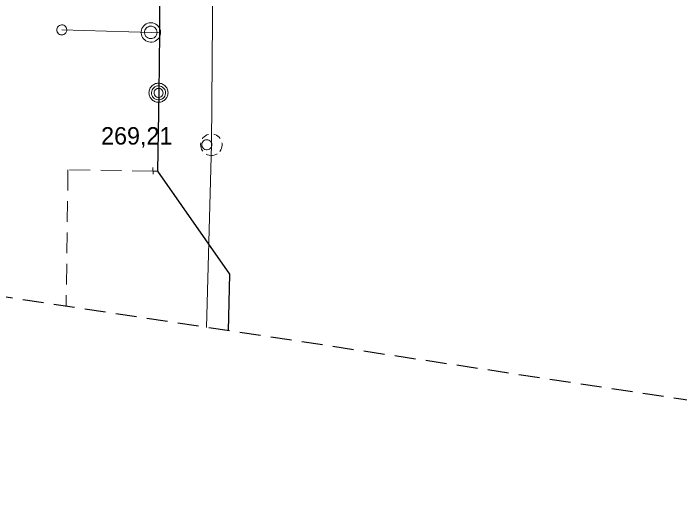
# Model space of a CAD drawing. Extents: x -732096 to -731933, y -1048703 to -1047964.
# Drawn here: x -731994.1 to -731963.51, y -1048703.26 to -1048680.91 of the extents above; entities that cross this region are included whole.
import ezdxf

# ---------------------------------------------------------------- set-up
doc = ezdxf.new("R2010")
doc.units = 0
doc.header["$LTSCALE"] = 0.32
doc.linetypes.add('MEDIUM_DASHED', pattern=[4.5, 3, -1.5])
doc.layers.add('1', color=7, linetype='Continuous')
for name, color, linetype, lineweight in [('18', 7, 'Continuous', 13), ('20', 7, 'Continuous', 13), ('63', 7, 'MEDIUM_DASHED', 25), ('8', 7, 'Continuous', 13)]:
    doc.layers.add(name, color=color, linetype=linetype, lineweight=lineweight)

msp = doc.modelspace()

# ---------------------------------------------------------------- linework, layer by layer
at = {"layer": '18'}
for points in [[(-731985.142, -1048686.473), (-731985.213, -1048686.499), (-731985.281, -1048686.536), (-731985.342, -1048686.583), (-731985.395, -1048686.639), (-731985.419, -1048686.672)], [(-731984.605, -1048686.668), (-731984.654, -1048686.609), (-731984.711, -1048686.558), (-731984.775, -1048686.515), (-731984.845, -1048686.484), (-731984.894, -1048686.469)], [(-731985.496, -1048686.856), (-731985.504, -1048686.933), (-731985.5, -1048687.01), (-731985.485, -1048687.086), (-731985.458, -1048687.157), (-731985.419, -1048687.224), (-731985.404, -1048687.247)], [(-731984.624, -1048687.254), (-731984.581, -1048687.19), (-731984.549, -1048687.12), (-731984.528, -1048687.046), (-731984.518, -1048686.97), (-731984.521, -1048686.893), (-731984.527, -1048686.858)], [(-731985.25, -1048687.379), (-731985.181, -1048687.412), (-731985.106, -1048687.433), (-731985.03, -1048687.441), (-731984.953, -1048687.438), (-731984.878, -1048687.423), (-731984.805, -1048687.397), (-731984.744, -1048687.363)]]:
    msp.add_lwpolyline(points, dxfattribs=at)
msp.add_lwpolyline([(-731984.988, -1048686.949), (-731984.994, -1048686.897), (-731985.012, -1048686.847), (-731985.04, -1048686.803), (-731985.078, -1048686.766), (-731985.123, -1048686.739), (-731985.173, -1048686.723), (-731985.225, -1048686.718), (-731985.277, -1048686.725), (-731985.326, -1048686.744), (-731985.37, -1048686.774), (-731985.405, -1048686.813), (-731985.431, -1048686.858), (-731985.446, -1048686.909), (-731985.449, -1048686.961), (-731985.441, -1048687.013), (-731985.42, -1048687.061), (-731985.39, -1048687.104), (-731985.35, -1048687.139), (-731985.304, -1048687.163), (-731985.253, -1048687.177), (-731985.201, -1048687.179), (-731985.149, -1048687.169), (-731985.101, -1048687.147), (-731985.059, -1048687.115), (-731985.026, -1048687.075), (-731985.002, -1048687.028), (-731984.99, -1048686.977)], close=True, dxfattribs=at)
at = {"layer": '20'}
msp.add_line((-731985.238, -1048695.344), (-731985, -1048686.94), dxfattribs=at)
msp.add_line((-731985.238, -1048695.344), (-731985, -1048686.94), dxfattribs=at)
msp.add_lwpolyline([(-731985, -1048686.94), (-731984.895, -1048673.539), (-731984.774, -1048658.239), (-731984.62, -1048638.44)], dxfattribs=at)
msp.add_lwpolyline([(-731985, -1048686.94), (-731984.895, -1048673.539), (-731984.774, -1048658.239), (-731984.62, -1048638.44)], dxfattribs=at)
at = {"layer": '63'}
msp.add_lwpolyline([(-732027.835, -1048396.578), (-731958.19, -1048580.745), (-731958.189, -1048580.746), (-731932.909, -1048703.246), (-731932.908, -1048703.248), (-731932.909, -1048703.25), (-731932.909, -1048703.251), (-731932.91, -1048703.253), (-731932.911, -1048703.255), (-731932.913, -1048703.256), (-731932.914, -1048703.257), (-731932.916, -1048703.257), (-731932.918, -1048703.258), (-731932.92, -1048703.258), (-732030.18, -1048688.546), (-732030.182, -1048688.545), (-732030.184, -1048688.545), (-732030.185, -1048688.543), (-732030.186, -1048688.542), (-732030.187, -1048688.54), (-732030.188, -1048688.538), (-732095.318, -1048413.733)], dxfattribs=at)
at = {"layer": '8'}
for p, q in [((-731987.687, -1048688.304), (-731987.693, -1048688)), ((-731987.487, -1048688.16), (-731987.69, -1048688.159))]:
    msp.add_line(p, q, dxfattribs=at)
at = {"layer": '8', "lineweight": 25}
for points in [[(-731986.969, -1048642.05), (-731986.984, -1048644.243), (-731987.12, -1048663.55), (-731987.35, -1048670.27), (-731987.388, -1048681.801), (-731987.43, -1048684.57)], [(-731987.43, -1048684.57), (-731987.487, -1048688.16), (-731984.18, -1048692.889), (-731984.235, -1048695.496)]]:
    msp.add_lwpolyline(points, dxfattribs=at)
at = {"layer": '8'}
for points in [[(-731987.79, -1048681.342), (-731987.863, -1048681.348), (-731987.934, -1048681.366), (-731988.001, -1048681.395), (-731988.062, -1048681.435), (-731988.117, -1048681.484), (-731988.162, -1048681.541), (-731988.197, -1048681.605), (-731988.222, -1048681.674), (-731988.235, -1048681.746), (-731988.236, -1048681.82), (-731988.225, -1048681.892), (-731988.202, -1048681.962), (-731988.169, -1048682.026), (-731988.125, -1048682.085), (-731988.072, -1048682.136), (-731988.012, -1048682.177), (-731987.945, -1048682.208), (-731987.875, -1048682.228), (-731987.802, -1048682.236), (-731987.729, -1048682.233), (-731987.658, -1048682.217), (-731987.59, -1048682.19), (-731987.527, -1048682.152), (-731987.472, -1048682.104), (-731987.425, -1048682.048), (-731987.388, -1048681.985), (-731987.361, -1048681.917), (-731987.346, -1048681.845), (-731987.343, -1048681.772), (-731987.352, -1048681.699), (-731987.373, -1048681.629), (-731987.405, -1048681.563), (-731987.447, -1048681.503), (-731987.498, -1048681.451), (-731987.558, -1048681.408), (-731987.623, -1048681.375), (-731987.693, -1048681.354), (-731987.765, -1048681.344)], [(-731992.11, -1048681.666), (-731992.105, -1048681.718), (-731992.089, -1048681.768), (-731992.062, -1048681.813), (-731992.026, -1048681.851), (-731991.981, -1048681.88), (-731991.932, -1048681.897), (-731991.88, -1048681.904), (-731991.828, -1048681.899), (-731991.778, -1048681.881), (-731991.733, -1048681.853), (-731991.697, -1048681.815), (-731991.67, -1048681.771), (-731991.653, -1048681.72), (-731991.649, -1048681.668), (-731991.655, -1048681.616), (-731991.674, -1048681.567), (-731991.703, -1048681.523), (-731991.742, -1048681.487), (-731991.787, -1048681.462), (-731991.838, -1048681.446), (-731991.89, -1048681.443), (-731991.942, -1048681.451), (-731991.991, -1048681.471), (-731992.034, -1048681.502), (-731992.068, -1048681.541), (-731992.093, -1048681.587), (-731992.107, -1048681.638)], [(-731987.79, -1048681.504), (-731987.848, -1048681.509), (-731987.904, -1048681.527), (-731987.955, -1048681.555), (-731987.999, -1048681.594), (-731988.035, -1048681.64), (-731988.06, -1048681.693), (-731988.074, -1048681.75), (-731988.076, -1048681.809), (-731988.066, -1048681.866), (-731988.044, -1048681.921), (-731988.012, -1048681.97), (-731987.971, -1048682.011), (-731987.922, -1048682.043), (-731987.867, -1048682.065), (-731987.81, -1048682.075), (-731987.751, -1048682.074), (-731987.694, -1048682.06), (-731987.641, -1048682.035), (-731987.595, -1048681.999), (-731987.556, -1048681.955), (-731987.528, -1048681.904), (-731987.51, -1048681.848), (-731987.504, -1048681.79), (-731987.51, -1048681.732), (-731987.527, -1048681.676), (-731987.556, -1048681.625), (-731987.595, -1048681.581), (-731987.641, -1048681.546), (-731987.694, -1048681.521), (-731987.751, -1048681.507)], [(-731987.113, -1048684.567), (-731987.119, -1048684.506), (-731987.137, -1048684.446), (-731987.166, -1048684.391), (-731987.205, -1048684.343), (-731987.252, -1048684.303), (-731987.306, -1048684.273), (-731987.365, -1048684.253), (-731987.427, -1048684.246), (-731987.489, -1048684.25), (-731987.549, -1048684.266), (-731987.604, -1048684.294), (-731987.654, -1048684.331), (-731987.695, -1048684.378), (-731987.727, -1048684.431), (-731987.747, -1048684.49), (-731987.757, -1048684.551), (-731987.754, -1048684.613), (-731987.739, -1048684.673), (-731987.713, -1048684.73), (-731987.677, -1048684.78), (-731987.631, -1048684.823), (-731987.579, -1048684.855), (-731987.521, -1048684.878), (-731987.46, -1048684.888), (-731987.398, -1048684.887), (-731987.337, -1048684.874), (-731987.28, -1048684.849), (-731987.229, -1048684.814), (-731987.185, -1048684.77), (-731987.151, -1048684.718), (-731987.127, -1048684.661), (-731987.115, -1048684.6)], [(-731987.227, -1048684.567), (-731987.233, -1048684.518), (-731987.25, -1048684.471), (-731987.278, -1048684.43), (-731987.316, -1048684.397), (-731987.36, -1048684.373), (-731987.408, -1048684.361), (-731987.458, -1048684.36), (-731987.506, -1048684.372), (-731987.551, -1048684.394), (-731987.589, -1048684.427), (-731987.618, -1048684.467), (-731987.637, -1048684.514), (-731987.644, -1048684.563), (-731987.639, -1048684.613), (-731987.622, -1048684.66), (-731987.595, -1048684.702), (-731987.558, -1048684.736), (-731987.515, -1048684.76), (-731987.467, -1048684.774), (-731987.417, -1048684.775), (-731987.368, -1048684.765), (-731987.323, -1048684.743), (-731987.284, -1048684.711), (-731987.254, -1048684.672), (-731987.235, -1048684.626), (-731987.227, -1048684.576)]]:
    msp.add_lwpolyline(points, close=True, dxfattribs=at)
for points in [[(-731987.388, -1048681.801), (-731987.78, -1048681.79), (-731991.879, -1048681.664)], [(-731987, -1048684.559), (-731987.002, -1048684.514), (-731987.009, -1048684.469), (-731987.021, -1048684.424), (-731987.037, -1048684.382), (-731987.058, -1048684.341), (-731987.083, -1048684.302), (-731987.112, -1048684.267), (-731987.144, -1048684.234), (-731987.18, -1048684.206), (-731987.218, -1048684.181), (-731987.259, -1048684.16), (-731987.302, -1048684.143), (-731987.346, -1048684.131), (-731987.391, -1048684.124), (-731987.437, -1048684.122), (-731987.483, -1048684.124), (-731987.528, -1048684.131), (-731987.572, -1048684.143), (-731987.615, -1048684.16), (-731987.656, -1048684.181), (-731987.694, -1048684.206), (-731987.73, -1048684.234), (-731987.762, -1048684.267), (-731987.791, -1048684.302), (-731987.816, -1048684.341), (-731987.837, -1048684.382), (-731987.853, -1048684.424), (-731987.865, -1048684.469), (-731987.872, -1048684.514), (-731987.875, -1048684.56), (-731987.872, -1048684.605), (-731987.865, -1048684.65), (-731987.853, -1048684.695), (-731987.837, -1048684.737), (-731987.816, -1048684.778), (-731987.791, -1048684.817), (-731987.762, -1048684.852), (-731987.73, -1048684.885), (-731987.694, -1048684.913), (-731987.656, -1048684.938), (-731987.615, -1048684.959), (-731987.572, -1048684.976), (-731987.528, -1048684.987), (-731987.483, -1048684.995), (-731987.437, -1048684.997), (-731987.391, -1048684.995), (-731987.346, -1048684.987), (-731987.302, -1048684.976), (-731987.259, -1048684.959), (-731987.218, -1048684.938), (-731987.18, -1048684.913), (-731987.144, -1048684.885), (-731987.112, -1048684.852), (-731987.083, -1048684.817), (-731987.058, -1048684.778), (-731987.037, -1048684.737), (-731987.021, -1048684.695), (-731987.009, -1048684.65), (-731987.002, -1048684.605), (-731987, -1048684.56)]]:
    msp.add_lwpolyline(points, dxfattribs=at)
at = {"layer": '8', "linetype": 'MEDIUM_DASHED'}
msp.add_lwpolyline([(-731987.69, -1048688.159), (-731991.594, -1048688.099), (-731991.68, -1048694.37)], dxfattribs=at)

# ---------------------------------------------------------------- texts
at = {"layer": '1'}
msp.add_text('269,21', height=0.8, dxfattribs=at).set_placement((-731990.073, -1048686.942))

doc.saveas('drawing.dxf')
